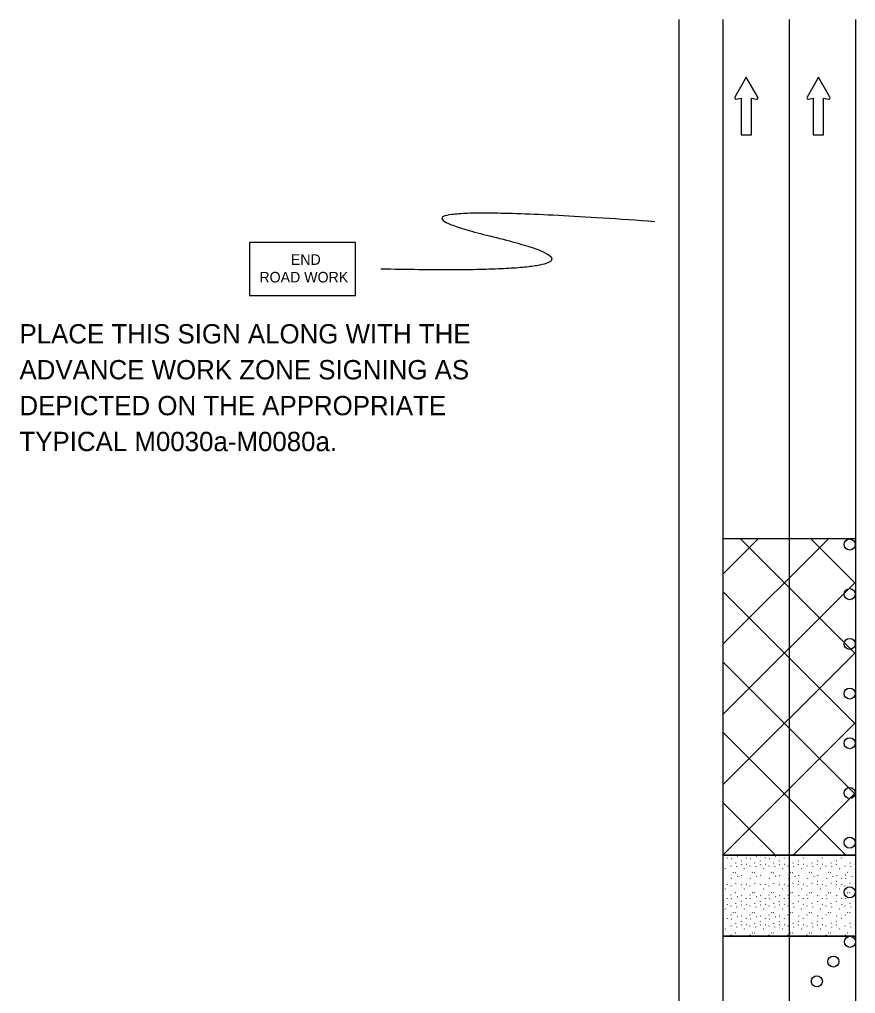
# Model space of a CAD drawing. Extents: x 16735 to 19504, y 6970 to 8243.
# Drawn here: x 17762.4 to 18065.1, y 7838.5 to 8191.4 of the extents above; entities that cross this region are included whole.
import ezdxf

# ---------------------------------------------------------------- set-up
doc = ezdxf.new("R2010")
doc.units = 0
for name, color, linetype in [('ALI_LEGAL_EX', 7, 'Continuous'), ('MT_SCRATCH_LEVEL_A', 7, 'Continuous'), ('MT_SCRATCH_LEVEL_E', 7, 'Continuous'), ('PAVT_EDGE_EX', 7, 'Continuous'), ('TRAFFIC_SIGNS_PR', 7, 'Continuous')]:
    doc.layers.add(name, color=color, linetype=linetype)

msp = doc.modelspace()

# ---------------------------------------------------------------- linework, layer by layer
at = {"layer": 'ALI_LEGAL_EX'}
for p, q in [((18041.08, 8191.4), (18041.08, 7362.22)), ((18065.08, 8191.4), (18065.08, 7362.22)), ((18065.08, 8191.4), (18065.08, 7362.22))]:
    msp.add_line(p, q, dxfattribs=at)
for points in [[(18041.08, 8191.4), (18041.08, 8166.4)], [(18065.08, 8191.4), (18065.08, 8166.4)], [(18041.08, 8091.4), (18041.08, 8066.4)], [(18065.08, 8091.4), (18065.08, 8066.4)], [(18041.08, 7991.4), (18041.08, 7966.4)], [(18065.08, 7991.4), (18065.08, 7966.4)], [(18041.08, 7891.4), (18041.08, 7866.4)], [(18065.08, 7891.4), (18065.08, 7866.4)]]:
    msp.add_lwpolyline(points, dxfattribs=at)
at = {"layer": 'MT_SCRATCH_LEVEL_A'}
for p, q in [((18065.08, 8003.21), (18017.08, 8003.21)), ((18065.08, 7888.68), (18017.08, 7888.68)), ((18065.08, 7859.25), (18017.08, 7859.25))]:
    msp.add_line(p, q, dxfattribs=at)
at = {"layer": 'MT_SCRATCH_LEVEL_E'}
for p, q in [((18025.54, 8170.46), (18021.43, 8163.22)), ((18025.54, 8170.46), (18021.43, 8163.22)), ((18029.69, 8163.22), (18025.54, 8170.46)), ((18029.69, 8163.22), (18025.54, 8170.46)), ((18051.65, 8170.46), (18047.54, 8163.22)), ((18051.65, 8170.46), (18047.54, 8163.22)), ((18055.8, 8163.22), (18051.65, 8170.46)), ((18055.8, 8163.22), (18051.65, 8170.46)), ((18021.91, 8162.54), (18023.69, 8162.86)), ((18021.91, 8162.54), (18023.69, 8162.86)), ((18023.69, 8162.86), (18023.69, 8149.6)), ((18023.69, 8162.86), (18023.69, 8149.6)), ((18027.43, 8149.6), (18027.43, 8162.86)), ((18027.43, 8162.86), (18029.21, 8162.54)), ((18027.43, 8149.6), (18027.43, 8162.86)), ((18027.43, 8162.86), (18029.21, 8162.54)), ((18048.02, 8162.54), (18049.8, 8162.86)), ((18048.02, 8162.54), (18049.8, 8162.86)), ((18049.8, 8162.86), (18049.8, 8149.6)), ((18049.8, 8162.86), (18049.8, 8149.6)), ((18053.54, 8149.6), (18053.54, 8162.86)), ((18053.54, 8162.86), (18055.32, 8162.54)), ((18053.54, 8149.6), (18053.54, 8162.86)), ((18053.54, 8162.86), (18055.32, 8162.54)), ((18023.69, 8149.6), (18027.43, 8149.6)), ((18023.69, 8149.6), (18027.43, 8149.6)), ((18049.8, 8149.6), (18053.54, 8149.6)), ((18049.8, 8149.6), (18053.54, 8149.6))]:
    msp.add_line(p, q, dxfattribs=at)
for centre, start, end in [((18021.84, 8163), 150.4248, 279.9638), ((18021.84, 8163), 150.4248, 279.9638), ((18029.28, 8163), 260.0362, 29.7731), ((18029.28, 8163), 260.0362, 29.7731), ((18047.94, 8163), 150.4248, 279.9638), ((18047.94, 8163), 150.4248, 279.9638), ((18055.39, 8163), 260.0362, 29.7731), ((18055.39, 8163), 260.0362, 29.7731)]:
    msp.add_arc(centre, 0.463, start, end, dxfattribs=at)
at = {"layer": 'PAVT_EDGE_EX'}
for p, q in [((18001.08, 8191.4), (18001.08, 7362.22)), ((18017.08, 8191.4), (18017.08, 7362.22)), ((18017.08, 8191.4), (18017.08, 7362.22)), ((18065.08, 8003.21), (18017.08, 8003.21)), ((18017.08, 8003.21), (18017.08, 7888.68)), ((18017.08, 7990.5), (18029.79, 8003.21)), ((18017.08, 7965.04), (18055.25, 8003.21)), ((18065.08, 7961.59), (18023.46, 8003.21)), ((18065.08, 7987.05), (18048.91, 8003.21)), ((18017.08, 7939.59), (18065.08, 7987.59)), ((18065.08, 7936.14), (18017.08, 7984.14)), ((18017.08, 7914.13), (18065.08, 7962.13)), ((18065.08, 7910.68), (18017.08, 7958.68)), ((18017.08, 7888.68), (18065.08, 7936.68)), ((18061.63, 7888.68), (18017.08, 7933.22)), ((18042.53, 7888.68), (18065.08, 7911.22)), ((18036.17, 7888.68), (18017.08, 7907.77)), ((18017.08, 7888.68), (18065.08, 7888.68)), ((18065.08, 7888.68), (18017.08, 7888.68)), ((18017.08, 7888.68), (18017.08, 7859.25)), ((18017.08, 7888.68), (18017.08, 7888.68)), ((18018.58, 7887.63), (18018.63, 7887.55)), ((18020.1, 7887.49), (18020.16, 7887.41)), ((18022.4, 7888.3), (18022.45, 7888.23)), ((18023.84, 7888.45), (18023.9, 7888.57)), ((18025.46, 7887.63), (18025.51, 7887.55)), ((18026.99, 7887.49), (18027.04, 7887.41)), ((18029.28, 7888.3), (18029.33, 7888.23)), ((18030.73, 7888.45), (18030.78, 7888.57)), ((18032.35, 7887.63), (18032.4, 7887.55)), ((18033.88, 7887.49), (18033.93, 7887.41)), ((18036.17, 7888.3), (18036.22, 7888.23)), ((18037.62, 7888.45), (18037.67, 7888.57)), ((18039.24, 7887.63), (18039.29, 7887.55)), ((18040.77, 7887.49), (18040.82, 7887.41)), ((18043.06, 7888.3), (18043.11, 7888.23)), ((18044.51, 7888.45), (18044.56, 7888.57)), ((18046.12, 7887.63), (18046.18, 7887.55)), ((18047.65, 7887.49), (18047.71, 7887.41)), ((18049.94, 7888.3), (18050, 7888.23)), ((18051.39, 7888.45), (18051.45, 7888.57)), ((18053.01, 7887.63), (18053.06, 7887.55)), ((18054.54, 7887.49), (18054.59, 7887.41)), ((18056.83, 7888.3), (18056.88, 7888.23)), ((18058.28, 7888.45), (18058.33, 7888.57)), ((18059.9, 7887.63), (18059.95, 7887.55)), ((18061.43, 7887.49), (18061.48, 7887.41)), ((18063.72, 7888.3), (18063.77, 7888.23)), ((18018.01, 7883.66), (18018.06, 7883.78)), ((18018.62, 7885.42), (18018.67, 7885.34)), ((18019.9, 7884.84), (18019.92, 7884.72)), ((18021.75, 7885.7), (18021.8, 7885.81)), ((18021.94, 7884.5), (18021.99, 7884.42)), ((18023.67, 7886.57), (18023.72, 7886.49)), ((18023.72, 7885.17), (18023.77, 7885.28)), ((18024.89, 7883.66), (18024.94, 7883.78)), ((18025.51, 7885.42), (18025.56, 7885.34)), ((18026.79, 7884.84), (18026.81, 7884.72)), ((18028.63, 7885.7), (18028.69, 7885.81)), ((18028.82, 7884.5), (18028.87, 7884.42)), ((18030.56, 7886.57), (18030.61, 7886.49)), ((18030.6, 7885.17), (18030.65, 7885.28)), ((18031.78, 7883.66), (18031.83, 7883.78)), ((18032.4, 7885.42), (18032.45, 7885.34)), ((18033.68, 7884.84), (18033.69, 7884.72)), ((18035.52, 7885.7), (18035.57, 7885.81)), ((18035.71, 7884.5), (18035.76, 7884.42)), ((18037.45, 7886.57), (18037.5, 7886.49)), ((18037.49, 7885.17), (18037.54, 7885.28)), ((18038.67, 7883.66), (18038.72, 7883.78)), ((18039.29, 7885.42), (18039.34, 7885.34)), ((18040.57, 7884.84), (18040.58, 7884.72)), ((18042.41, 7885.7), (18042.46, 7885.81)), ((18042.6, 7884.5), (18042.65, 7884.42)), ((18044.33, 7886.57), (18044.39, 7886.49)), ((18044.38, 7885.17), (18044.43, 7885.28)), ((18045.56, 7883.66), (18045.61, 7883.78)), ((18046.17, 7885.42), (18046.23, 7885.34)), ((18047.46, 7884.84), (18047.47, 7884.72)), ((18049.3, 7885.7), (18049.35, 7885.81)), ((18049.49, 7884.5), (18049.54, 7884.42)), ((18051.22, 7886.57), (18051.27, 7886.49)), ((18051.26, 7885.17), (18051.32, 7885.28)), ((18052.44, 7883.66), (18052.49, 7883.78)), ((18053.06, 7885.42), (18053.11, 7885.34)), ((18054.34, 7884.84), (18054.36, 7884.72)), ((18056.18, 7885.7), (18056.24, 7885.81)), ((18056.37, 7884.5), (18056.42, 7884.42)), ((18058.11, 7886.57), (18058.16, 7886.49)), ((18058.15, 7885.17), (18058.2, 7885.28)), ((18059.33, 7883.66), (18059.38, 7883.78)), ((18059.95, 7885.42), (18060, 7885.34)), ((18061.23, 7884.84), (18061.24, 7884.72)), ((18063.07, 7885.7), (18063.12, 7885.81)), ((18063.26, 7884.5), (18063.31, 7884.42)), ((18065, 7886.57), (18065.05, 7886.49)), ((18065.04, 7885.17), (18065.08, 7885.25)), ((18018.58, 7880.34), (18018.63, 7880.26)), ((18020.03, 7881.47), (18020.08, 7881.58)), ((18020.1, 7880.2), (18020.16, 7880.12)), ((18020.79, 7882.43), (18020.84, 7882.35)), ((18021.53, 7882.4), (18021.58, 7882.32)), ((18022.4, 7881.02), (18022.45, 7880.94)), ((18023.84, 7881.17), (18023.9, 7881.29)), ((18025.46, 7880.34), (18025.51, 7880.26)), ((18026.91, 7881.47), (18026.96, 7881.58)), ((18026.99, 7880.2), (18027.04, 7880.12)), ((18027.68, 7882.43), (18027.73, 7882.35)), ((18028.41, 7882.4), (18028.47, 7882.32)), ((18029.28, 7881.02), (18029.33, 7880.94)), ((18030.73, 7881.17), (18030.78, 7881.29)), ((18032.35, 7880.34), (18032.4, 7880.26)), ((18033.8, 7881.47), (18033.85, 7881.58)), ((18033.88, 7880.2), (18033.93, 7880.12)), ((18034.56, 7882.43), (18034.62, 7882.35)), ((18035.3, 7882.4), (18035.35, 7882.32)), ((18036.17, 7881.02), (18036.22, 7880.94)), ((18037.62, 7881.17), (18037.67, 7881.29)), ((18039.24, 7880.34), (18039.29, 7880.26)), ((18040.69, 7881.47), (18040.74, 7881.58)), ((18040.77, 7880.2), (18040.82, 7880.12)), ((18041.45, 7882.43), (18041.5, 7882.35)), ((18042.19, 7882.4), (18042.24, 7882.32)), ((18043.06, 7881.02), (18043.11, 7880.94)), ((18044.51, 7881.17), (18044.56, 7881.29)), ((18046.12, 7880.34), (18046.18, 7880.26)), ((18047.58, 7881.47), (18047.63, 7881.58)), ((18047.65, 7880.2), (18047.71, 7880.12)), ((18048.34, 7882.43), (18048.39, 7882.35)), ((18049.08, 7882.4), (18049.13, 7882.32)), ((18049.94, 7881.02), (18050, 7880.94)), ((18051.39, 7881.17), (18051.45, 7881.29)), ((18053.01, 7880.34), (18053.06, 7880.26)), ((18054.46, 7881.47), (18054.51, 7881.58)), ((18054.54, 7880.2), (18054.59, 7880.12)), ((18055.23, 7882.43), (18055.28, 7882.35)), ((18055.96, 7882.4), (18056.02, 7882.32)), ((18056.83, 7881.02), (18056.88, 7880.94)), ((18058.28, 7881.17), (18058.33, 7881.29)), ((18059.9, 7880.34), (18059.95, 7880.26)), ((18061.35, 7881.47), (18061.4, 7881.58)), ((18061.43, 7880.2), (18061.48, 7880.12)), ((18062.11, 7882.43), (18062.17, 7882.35)), ((18062.85, 7882.4), (18062.9, 7882.32)), ((18063.72, 7881.02), (18063.77, 7880.94)), ((18018.01, 7876.38), (18018.06, 7876.5)), ((18018.62, 7878.13), (18018.67, 7878.05)), ((18019.9, 7877.56), (18019.92, 7877.44)), ((18021.75, 7878.41), (18021.8, 7878.53)), ((18021.94, 7877.21), (18021.99, 7877.14)), ((18023.67, 7879.28), (18023.72, 7879.2)), ((18023.72, 7877.88), (18023.77, 7878)), ((18024.89, 7876.38), (18024.94, 7876.5)), ((18025.51, 7878.13), (18025.56, 7878.05)), ((18026.79, 7877.56), (18026.81, 7877.44)), ((18028.63, 7878.41), (18028.69, 7878.53)), ((18028.82, 7877.21), (18028.87, 7877.14)), ((18030.56, 7879.28), (18030.61, 7879.2)), ((18030.6, 7877.88), (18030.65, 7878)), ((18031.78, 7876.38), (18031.83, 7876.5)), ((18032.4, 7878.13), (18032.45, 7878.05)), ((18033.68, 7877.56), (18033.69, 7877.44)), ((18035.52, 7878.41), (18035.57, 7878.53)), ((18035.71, 7877.21), (18035.76, 7877.14)), ((18037.45, 7879.28), (18037.5, 7879.2)), ((18037.49, 7877.88), (18037.54, 7878)), ((18038.67, 7876.38), (18038.72, 7876.5)), ((18039.29, 7878.13), (18039.34, 7878.05)), ((18040.57, 7877.56), (18040.58, 7877.44)), ((18042.41, 7878.41), (18042.46, 7878.53)), ((18042.6, 7877.21), (18042.65, 7877.14)), ((18044.33, 7879.28), (18044.39, 7879.2)), ((18044.38, 7877.88), (18044.43, 7878)), ((18045.56, 7876.38), (18045.61, 7876.5)), ((18046.17, 7878.13), (18046.23, 7878.05)), ((18047.46, 7877.56), (18047.47, 7877.44)), ((18049.3, 7878.41), (18049.35, 7878.53)), ((18049.49, 7877.21), (18049.54, 7877.14)), ((18051.22, 7879.28), (18051.27, 7879.2)), ((18051.26, 7877.88), (18051.32, 7878)), ((18052.44, 7876.38), (18052.49, 7876.5)), ((18053.06, 7878.13), (18053.11, 7878.05)), ((18054.34, 7877.56), (18054.36, 7877.44)), ((18056.18, 7878.41), (18056.24, 7878.53)), ((18056.37, 7877.21), (18056.42, 7877.14)), ((18058.11, 7879.28), (18058.16, 7879.2)), ((18058.15, 7877.88), (18058.2, 7878)), ((18059.33, 7876.38), (18059.38, 7876.5)), ((18059.95, 7878.13), (18060, 7878.05)), ((18061.23, 7877.56), (18061.24, 7877.44)), ((18063.07, 7878.41), (18063.12, 7878.53)), ((18063.26, 7877.21), (18063.31, 7877.14)), ((18065, 7879.28), (18065.05, 7879.2)), ((18065.04, 7877.88), (18065.08, 7877.97)), ((18018.58, 7873.06), (18018.63, 7872.98)), ((18020.03, 7874.18), (18020.08, 7874.3)), ((18020.1, 7872.92), (18020.16, 7872.84)), ((18020.79, 7875.14), (18020.84, 7875.07)), ((18021.53, 7875.11), (18021.58, 7875.03)), ((18022.4, 7873.73), (18022.45, 7873.66)), ((18023.84, 7873.89), (18023.9, 7874)), ((18025.46, 7873.06), (18025.51, 7872.98)), ((18026.91, 7874.18), (18026.96, 7874.3)), ((18026.99, 7872.92), (18027.04, 7872.84)), ((18027.68, 7875.14), (18027.73, 7875.07)), ((18028.41, 7875.11), (18028.47, 7875.03)), ((18029.28, 7873.73), (18029.33, 7873.66)), ((18030.73, 7873.89), (18030.78, 7874)), ((18032.35, 7873.06), (18032.4, 7872.98)), ((18033.8, 7874.18), (18033.85, 7874.3)), ((18033.88, 7872.92), (18033.93, 7872.84)), ((18034.56, 7875.14), (18034.62, 7875.07)), ((18035.3, 7875.11), (18035.35, 7875.03)), ((18036.17, 7873.73), (18036.22, 7873.66)), ((18037.62, 7873.89), (18037.67, 7874)), ((18039.24, 7873.06), (18039.29, 7872.98)), ((18040.69, 7874.18), (18040.74, 7874.3)), ((18040.77, 7872.92), (18040.82, 7872.84)), ((18041.45, 7875.14), (18041.5, 7875.07)), ((18042.19, 7875.11), (18042.24, 7875.03)), ((18043.06, 7873.73), (18043.11, 7873.66)), ((18044.51, 7873.89), (18044.56, 7874)), ((18046.12, 7873.06), (18046.18, 7872.98)), ((18047.58, 7874.18), (18047.63, 7874.3)), ((18047.65, 7872.92), (18047.71, 7872.84)), ((18048.34, 7875.14), (18048.39, 7875.07)), ((18049.08, 7875.11), (18049.13, 7875.03)), ((18049.94, 7873.73), (18050, 7873.66)), ((18051.39, 7873.89), (18051.45, 7874)), ((18053.01, 7873.06), (18053.06, 7872.98)), ((18054.46, 7874.18), (18054.51, 7874.3)), ((18054.54, 7872.92), (18054.59, 7872.84)), ((18055.23, 7875.14), (18055.28, 7875.07)), ((18055.96, 7875.11), (18056.02, 7875.03)), ((18056.83, 7873.73), (18056.88, 7873.66)), ((18058.28, 7873.89), (18058.33, 7874)), ((18059.9, 7873.06), (18059.95, 7872.98)), ((18061.35, 7874.18), (18061.4, 7874.3)), ((18061.43, 7872.92), (18061.48, 7872.84)), ((18062.11, 7875.14), (18062.17, 7875.07)), ((18062.85, 7875.11), (18062.9, 7875.03)), ((18063.72, 7873.73), (18063.77, 7873.66)), ((18018.01, 7869.09), (18018.06, 7869.21)), ((18018.62, 7870.85), (18018.67, 7870.77)), ((18019.9, 7870.27), (18019.92, 7870.15)), ((18021.75, 7871.13), (18021.8, 7871.24)), ((18021.94, 7869.93), (18021.99, 7869.85)), ((18023.67, 7872), (18023.72, 7871.92)), ((18023.72, 7870.6), (18023.77, 7870.71)), ((18024.89, 7869.09), (18024.94, 7869.21)), ((18025.51, 7870.85), (18025.56, 7870.77)), ((18026.79, 7870.27), (18026.81, 7870.15)), ((18028.63, 7871.13), (18028.69, 7871.24)), ((18028.82, 7869.93), (18028.87, 7869.85)), ((18030.56, 7872), (18030.61, 7871.92)), ((18030.6, 7870.6), (18030.65, 7870.71)), ((18031.78, 7869.09), (18031.83, 7869.21)), ((18032.4, 7870.85), (18032.45, 7870.77)), ((18033.68, 7870.27), (18033.69, 7870.15)), ((18035.52, 7871.13), (18035.57, 7871.24)), ((18035.71, 7869.93), (18035.76, 7869.85)), ((18037.45, 7872), (18037.5, 7871.92)), ((18037.49, 7870.6), (18037.54, 7870.71)), ((18038.67, 7869.09), (18038.72, 7869.21)), ((18039.29, 7870.85), (18039.34, 7870.77)), ((18040.57, 7870.27), (18040.58, 7870.15)), ((18042.41, 7871.13), (18042.46, 7871.24)), ((18042.6, 7869.93), (18042.65, 7869.85)), ((18044.33, 7872), (18044.39, 7871.92)), ((18044.38, 7870.6), (18044.43, 7870.71)), ((18045.56, 7869.09), (18045.61, 7869.21)), ((18046.17, 7870.85), (18046.23, 7870.77)), ((18047.46, 7870.27), (18047.47, 7870.15)), ((18049.3, 7871.13), (18049.35, 7871.24)), ((18049.49, 7869.93), (18049.54, 7869.85)), ((18051.22, 7872), (18051.27, 7871.92)), ((18051.26, 7870.6), (18051.32, 7870.71)), ((18052.44, 7869.09), (18052.49, 7869.21)), ((18053.06, 7870.85), (18053.11, 7870.77)), ((18054.34, 7870.27), (18054.36, 7870.15)), ((18056.18, 7871.13), (18056.24, 7871.24)), ((18056.37, 7869.93), (18056.42, 7869.85)), ((18058.11, 7872), (18058.16, 7871.92)), ((18058.15, 7870.6), (18058.2, 7870.71)), ((18059.33, 7869.09), (18059.38, 7869.21)), ((18059.95, 7870.85), (18060, 7870.77)), ((18061.23, 7870.27), (18061.24, 7870.15)), ((18063.07, 7871.13), (18063.12, 7871.24)), ((18063.26, 7869.93), (18063.31, 7869.85)), ((18065, 7872), (18065.05, 7871.92)), ((18065.04, 7870.6), (18065.08, 7870.68)), ((18018.58, 7865.77), (18018.63, 7865.69)), ((18020.03, 7866.9), (18020.08, 7867.01)), ((18020.1, 7865.63), (18020.16, 7865.55)), ((18020.79, 7867.86), (18020.84, 7867.78)), ((18021.53, 7867.83), (18021.58, 7867.75)), ((18022.4, 7866.45), (18022.45, 7866.37)), ((18023.84, 7866.6), (18023.9, 7866.72)), ((18025.46, 7865.77), (18025.51, 7865.69)), ((18026.91, 7866.9), (18026.96, 7867.01)), ((18026.99, 7865.63), (18027.04, 7865.55)), ((18027.68, 7867.86), (18027.73, 7867.78)), ((18028.41, 7867.83), (18028.47, 7867.75)), ((18029.28, 7866.45), (18029.33, 7866.37)), ((18030.73, 7866.6), (18030.78, 7866.72)), ((18032.35, 7865.77), (18032.4, 7865.69)), ((18033.8, 7866.9), (18033.85, 7867.01)), ((18033.88, 7865.63), (18033.93, 7865.55)), ((18034.56, 7867.86), (18034.62, 7867.78)), ((18035.3, 7867.83), (18035.35, 7867.75)), ((18036.17, 7866.45), (18036.22, 7866.37)), ((18037.62, 7866.6), (18037.67, 7866.72)), ((18039.24, 7865.77), (18039.29, 7865.69)), ((18040.69, 7866.9), (18040.74, 7867.01)), ((18040.77, 7865.63), (18040.82, 7865.55)), ((18041.45, 7867.86), (18041.5, 7867.78)), ((18042.19, 7867.83), (18042.24, 7867.75)), ((18043.06, 7866.45), (18043.11, 7866.37)), ((18044.51, 7866.6), (18044.56, 7866.72)), ((18046.12, 7865.77), (18046.18, 7865.69)), ((18047.58, 7866.9), (18047.63, 7867.01)), ((18047.65, 7865.63), (18047.71, 7865.55)), ((18048.34, 7867.86), (18048.39, 7867.78)), ((18049.08, 7867.83), (18049.13, 7867.75)), ((18049.94, 7866.45), (18050, 7866.37)), ((18051.39, 7866.6), (18051.45, 7866.72)), ((18053.01, 7865.77), (18053.06, 7865.69)), ((18054.46, 7866.9), (18054.51, 7867.01)), ((18054.54, 7865.63), (18054.59, 7865.55)), ((18055.23, 7867.86), (18055.28, 7867.78)), ((18055.96, 7867.83), (18056.02, 7867.75)), ((18056.83, 7866.45), (18056.88, 7866.37)), ((18058.28, 7866.6), (18058.33, 7866.72)), ((18059.9, 7865.77), (18059.95, 7865.69)), ((18061.35, 7866.9), (18061.4, 7867.01)), ((18061.43, 7865.63), (18061.48, 7865.55)), ((18062.11, 7867.86), (18062.17, 7867.78)), ((18062.85, 7867.83), (18062.9, 7867.75)), ((18063.72, 7866.45), (18063.77, 7866.37)), ((18018.62, 7863.56), (18018.67, 7863.49)), ((18019.9, 7862.99), (18019.92, 7862.87)), ((18021.75, 7863.84), (18021.8, 7863.96)), ((18021.94, 7862.64), (18021.99, 7862.57)), ((18023.67, 7864.71), (18023.72, 7864.63)), ((18023.72, 7863.31), (18023.77, 7863.43)), ((18025.51, 7863.56), (18025.56, 7863.49)), ((18026.79, 7862.99), (18026.81, 7862.87)), ((18028.63, 7863.84), (18028.69, 7863.96)), ((18028.82, 7862.64), (18028.87, 7862.57)), ((18030.56, 7864.71), (18030.61, 7864.63)), ((18030.6, 7863.31), (18030.65, 7863.43)), ((18032.4, 7863.56), (18032.45, 7863.49)), ((18033.68, 7862.99), (18033.69, 7862.87)), ((18035.52, 7863.84), (18035.57, 7863.96)), ((18035.71, 7862.64), (18035.76, 7862.57)), ((18037.45, 7864.71), (18037.5, 7864.63)), ((18037.49, 7863.31), (18037.54, 7863.43)), ((18039.29, 7863.56), (18039.34, 7863.49)), ((18040.57, 7862.99), (18040.58, 7862.87)), ((18042.41, 7863.84), (18042.46, 7863.96)), ((18042.6, 7862.64), (18042.65, 7862.57)), ((18044.33, 7864.71), (18044.39, 7864.63)), ((18044.38, 7863.31), (18044.43, 7863.43)), ((18046.17, 7863.56), (18046.23, 7863.49)), ((18047.46, 7862.99), (18047.47, 7862.87)), ((18049.3, 7863.84), (18049.35, 7863.96)), ((18049.49, 7862.64), (18049.54, 7862.57)), ((18051.22, 7864.71), (18051.27, 7864.63)), ((18051.26, 7863.31), (18051.32, 7863.43)), ((18053.06, 7863.56), (18053.11, 7863.49)), ((18054.34, 7862.99), (18054.36, 7862.87)), ((18056.18, 7863.84), (18056.24, 7863.96)), ((18056.37, 7862.64), (18056.42, 7862.57)), ((18058.11, 7864.71), (18058.16, 7864.63)), ((18058.15, 7863.31), (18058.2, 7863.43)), ((18059.95, 7863.56), (18060, 7863.49)), ((18061.23, 7862.99), (18061.24, 7862.87)), ((18063.07, 7863.84), (18063.12, 7863.96)), ((18063.26, 7862.64), (18063.31, 7862.57)), ((18065, 7864.71), (18065.05, 7864.63)), ((18065.04, 7863.31), (18065.08, 7863.4)), ((18017.08, 7859.25), (18065.08, 7859.25)), ((18018.01, 7861.81), (18018.06, 7861.93)), ((18020.03, 7859.61), (18020.08, 7859.73)), ((18020.79, 7860.57), (18020.84, 7860.49)), ((18021.53, 7860.54), (18021.58, 7860.47)), ((18023.84, 7859.32), (18023.9, 7859.43)), ((18024.89, 7861.81), (18024.94, 7861.93)), ((18026.91, 7859.61), (18026.96, 7859.73)), ((18027.68, 7860.57), (18027.73, 7860.49)), ((18028.41, 7860.54), (18028.47, 7860.47)), ((18030.73, 7859.32), (18030.78, 7859.43)), ((18031.78, 7861.81), (18031.83, 7861.93)), ((18033.8, 7859.61), (18033.85, 7859.73)), ((18034.56, 7860.57), (18034.62, 7860.49)), ((18035.3, 7860.54), (18035.35, 7860.47)), ((18037.62, 7859.32), (18037.67, 7859.43)), ((18038.67, 7861.81), (18038.72, 7861.93)), ((18040.69, 7859.61), (18040.74, 7859.73)), ((18041.45, 7860.57), (18041.5, 7860.49)), ((18042.19, 7860.54), (18042.24, 7860.47)), ((18044.51, 7859.32), (18044.56, 7859.43)), ((18045.56, 7861.81), (18045.61, 7861.93)), ((18047.58, 7859.61), (18047.63, 7859.73)), ((18048.34, 7860.57), (18048.39, 7860.49)), ((18049.08, 7860.54), (18049.13, 7860.47)), ((18051.39, 7859.32), (18051.45, 7859.43)), ((18052.44, 7861.81), (18052.49, 7861.93)), ((18054.46, 7859.61), (18054.51, 7859.73)), ((18055.23, 7860.57), (18055.28, 7860.49)), ((18055.96, 7860.54), (18056.02, 7860.47)), ((18058.28, 7859.32), (18058.33, 7859.43)), ((18059.33, 7861.81), (18059.38, 7861.93)), ((18061.35, 7859.61), (18061.4, 7859.73)), ((18062.11, 7860.57), (18062.17, 7860.49)), ((18062.85, 7860.54), (18062.9, 7860.47))]:
    msp.add_line(p, q, dxfattribs=at)
at = {"layer": 'TRAFFIC_SIGNS_PR'}
msp.add_lwpolyline([(17845.66, 8091.38), (17884.06, 8091.38), (17884.06, 8110.58), (17845.66, 8110.58)], close=True, dxfattribs=at)
for centre in [(18062.98, 8001.2), (18062.98, 7983.2), (18062.98, 7965.2), (18062.98, 7947.2), (18062.98, 7929.2), (18062.98, 7911.2), (18062.98, 7893.2), (18062.98, 7875.2), (18063.08, 7857.25), (18057.08, 7850.11), (18051.08, 7842.97)]:
    msp.add_circle(centre, 2, dxfattribs=at)
msp.add_open_spline([(17992.47, 8118.15), (17877.24, 8126.39), (17991.15, 8098.81), (17893.21, 8100.98)], degree=2, dxfattribs=at)

# ---------------------------------------------------------------- texts
for s, height, p in [('END', 3.831, (17860.66, 8102.51)), ('ROAD WORK', 3.831, (17849.27, 8096.13)), ('PLACE THIS SIGN ALONG WITH THE', 7, (17762.4, 8074.02)), ('ADVANCE WORK ZONE SIGNING AS', 7, (17762.4, 8061.02)), ('DEPICTED ON THE APPROPRIATE', 7, (17762.4, 8048.02)), ('TYPICAL M0030a-M0080a.', 7, (17762.4, 8035.02))]:
    msp.add_text(s, height=height, dxfattribs=at).set_placement(p)

doc.saveas('drawing.dxf')
